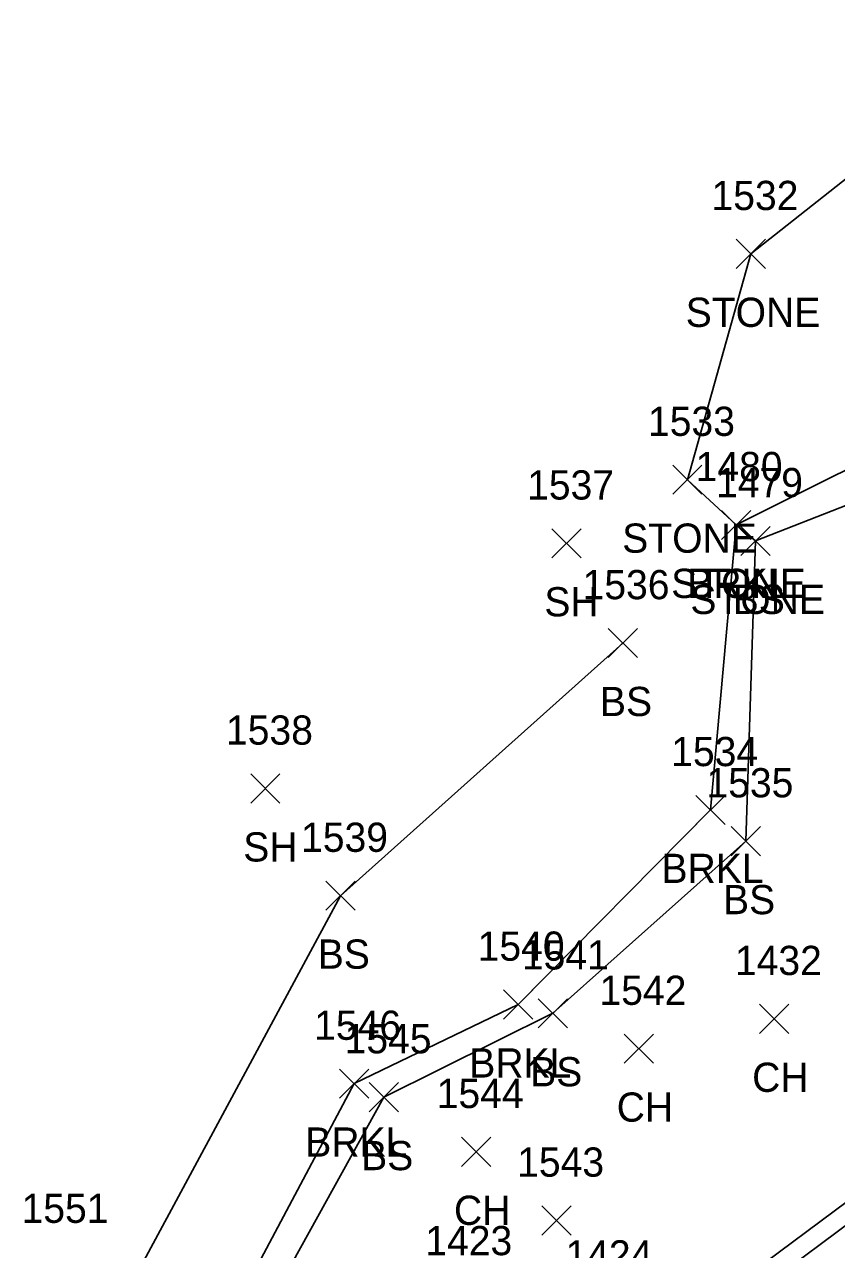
# Model space of a CAD drawing. Extents: x 1599840 to 1601211, y 518904 to 521989.
# Drawn here: x 1600682.3 to 1600737.9, y 521246 to 521329.9 of the extents above; entities that cross this region are included whole.
import ezdxf

# ---------------------------------------------------------------- set-up
doc = ezdxf.new("R2010")
doc.units = 0
for name, color, linetype in [('L_A', 7, 'Continuous'), ('L_I', 7, 'Continuous'), ('L_TIC', 7, 'Continuous'), ('LASF', 7, 'Continuous'), ('LAWE', 7, 'Continuous'), ('LELB', 7, 'Continuous')]:
    doc.layers.add(name, color=color, linetype=linetype)

msp = doc.modelspace()

# ---------------------------------------------------------------- linework, layer by layer
at = {"layer": 'L_TIC'}
for points in [[(1600731.014, 521313.218), (1600733.014, 521315.218)], [(1600733.014, 521313.218), (1600731.014, 521315.218)], [(1600726.669, 521297.755), (1600728.669, 521299.755)], [(1600728.669, 521297.755), (1600726.669, 521299.755)], [(1600726.669, 521297.755), (1600728.669, 521299.755)], [(1600728.669, 521297.755), (1600726.669, 521299.755)], [(1600730.017, 521294.657), (1600732.017, 521296.657)], [(1600732.017, 521294.657), (1600730.017, 521296.657)], [(1600730.017, 521294.657), (1600732.017, 521296.657)], [(1600732.017, 521294.657), (1600730.017, 521296.657)], [(1600718.395, 521293.397), (1600720.395, 521295.397)], [(1600720.395, 521293.397), (1600718.395, 521295.397)], [(1600731.332, 521293.559), (1600733.332, 521295.559)], [(1600733.332, 521293.559), (1600731.332, 521295.559)], [(1600731.332, 521293.559), (1600733.332, 521295.559)], [(1600733.332, 521293.559), (1600731.332, 521295.559)], [(1600722.247, 521286.571), (1600724.247, 521288.571)], [(1600724.247, 521286.571), (1600722.247, 521288.571)], [(1600697.789, 521276.613), (1600699.789, 521278.613)], [(1600699.789, 521276.613), (1600697.789, 521278.613)], [(1600728.255, 521275.143), (1600730.255, 521277.143)], [(1600730.255, 521275.143), (1600728.255, 521277.143)], [(1600730.67, 521273.005), (1600732.67, 521275.005)], [(1600732.67, 521273.005), (1600730.67, 521275.005)], [(1600702.935, 521269.274), (1600704.935, 521271.274)], [(1600704.935, 521269.274), (1600702.935, 521271.274)], [(1600715.099, 521261.819), (1600717.099, 521263.819)], [(1600717.099, 521261.819), (1600715.099, 521263.819)], [(1600717.471, 521261.22), (1600719.471, 521263.22)], [(1600719.471, 521261.22), (1600717.471, 521263.22)], [(1600732.615, 521260.84), (1600734.615, 521262.84)], [(1600734.615, 521260.84), (1600732.615, 521262.84)], [(1600723.346, 521258.798), (1600725.346, 521260.798)], [(1600725.346, 521258.798), (1600723.346, 521260.798)], [(1600703.876, 521256.404), (1600705.876, 521258.404)], [(1600705.876, 521256.404), (1600703.876, 521258.404)], [(1600705.906, 521255.479), (1600707.906, 521257.479)], [(1600707.906, 521255.479), (1600705.906, 521257.479)], [(1600712.21, 521251.733), (1600714.21, 521253.733)], [(1600714.21, 521251.733), (1600712.21, 521253.733)], [(1600717.714, 521247.034), (1600719.714, 521249.034)], [(1600719.714, 521247.034), (1600717.714, 521249.034)]]:
    msp.add_lwpolyline(points, dxfattribs=at)
at = {"layer": 'LASF'}
for points in [[(1600788.504, 521302.133), (1600797.248, 521300.149), (1600801.203, 521300.015), (1600804.381, 521299.912), (1600806.428, 521305.176), (1600805.239, 521316.786), (1600796.978, 521329.204), (1600794.865, 521329.922), (1600789.19, 521328.403), (1600773.997, 521324.831), (1600760.497, 521319.404), (1600745.632, 521315.291), (1600743.26, 521323.098), (1600732.014, 521314.218), (1600727.669, 521298.755)], [(1600787.733, 521301.588), (1600778.08, 521301.561), (1600769.876, 521302.473), (1600769.452, 521306.712), (1600761.198, 521309.066), (1600753.437, 521305.807), (1600746.621, 521300.165), (1600732.332, 521294.559), (1600731.017, 521295.657), (1600727.669, 521298.755)]]:
    msp.add_lwpolyline(points, dxfattribs=at)
at = {"layer": 'LAWE'}
for points in [[(1600788.504, 521302.133), (1600779.639, 521306.578), (1600769.853, 521311.777), (1600761.009, 521310.636), (1600751.785, 521307.227), (1600745.14, 521302.726), (1600731.017, 521295.657), (1600729.255, 521276.143), (1600716.099, 521262.819), (1600704.876, 521257.404), (1600692.678, 521234.473)], [(1600710.084, 521218.612), (1600728.191, 521240.002), (1600744.345, 521252.061), (1600761.877, 521257.582), (1600767.454, 521262.572), (1600777.034, 521264.853), (1600779.729, 521268.746)]]:
    msp.add_lwpolyline(points, dxfattribs=at)
at = {"layer": 'LELB'}
for points in [[(1600708.733, 521220.076), (1600727.282, 521240.92), (1600743.422, 521252.915), (1600761.441, 521259.849), (1600767.997, 521266.834), (1600775.487, 521267.923), (1600778.299, 521269.516), (1600777.22, 521270.369), (1600777.984, 521271.944), (1600782.563, 521280.311), (1600784.373, 521283.656), (1600784.535, 521285.275), (1600784.988, 521289.181), (1600784.719, 521292.066), (1600785.198, 521295.053), (1600787.733, 521301.588)], [(1600732.332, 521294.559), (1600731.67, 521274.005), (1600718.471, 521262.22), (1600706.906, 521256.479), (1600694.411, 521233.895)], [(1600723.247, 521287.571), (1600703.935, 521270.274), (1600687.938, 521240.571)]]:
    msp.add_lwpolyline(points, dxfattribs=at)

# ---------------------------------------------------------------- texts
at = {"layer": 'L_A'}
for s, p in [('STONE', (1600727.557, 521309.218)), ('STONE', (1600723.212, 521293.755)), ('STONE', (1600723.212, 521293.755)), ('STONE', (1600726.561, 521290.657)), ('BRKL', (1600727.663, 521290.657)), ('SH', (1600717.883, 521289.397)), ('STONE', (1600727.875, 521289.559)), ('BS', (1600730.773, 521289.559)), ('BS', (1600721.688, 521282.571)), ('SH', (1600697.278, 521272.613)), ('BRKL', (1600725.901, 521271.143)), ('BS', (1600730.111, 521269.005)), ('BS', (1600702.376, 521265.274)), ('BRKL', (1600712.745, 521257.819)), ('BS', (1600716.912, 521257.22)), ('CH', (1600732.103, 521256.84)), ('CH', (1600722.835, 521254.798)), ('BRKL', (1600701.521, 521252.404)), ('BS', (1600705.347, 521251.479)), ('CH', (1600711.698, 521247.733))]:
    msp.add_text(s, height=2, dxfattribs=at).set_placement(p)
at = {"layer": 'L_I'}
for s, p in [('1532', (1600729.321, 521317.218)), ('1533', (1600724.976, 521301.755)), ('1533', (1600724.976, 521301.755)), ('1480', (1600728.238, 521298.657)), ('1480', (1600728.238, 521298.657)), ('1537', (1600716.703, 521297.397)), ('1479', (1600729.631, 521297.559)), ('1479', (1600729.631, 521297.559)), ('1536', (1600720.499, 521290.571)), ('1538', (1600696.097, 521280.613)), ('1534', (1600726.563, 521279.143)), ('1535', (1600728.977, 521277.005)), ('1539', (1600701.234, 521273.274)), ('1540', (1600713.32, 521265.819)), ('1541', (1600716.345, 521265.22)), ('1432', (1600730.923, 521264.84)), ('1542', (1600721.654, 521262.798)), ('1546', (1600702.128, 521260.404)), ('1545', (1600704.214, 521259.479)), ('1544', (1600710.517, 521255.733)), ('1543', (1600716.021, 521251.034)), ('1551', (1600682.105, 521247.87)), ('1423', (1600709.736, 521245.658)), ('1424', (1600719.325, 521244.679))]:
    msp.add_text(s, height=2, dxfattribs=at).set_placement(p)

doc.saveas('drawing.dxf')
